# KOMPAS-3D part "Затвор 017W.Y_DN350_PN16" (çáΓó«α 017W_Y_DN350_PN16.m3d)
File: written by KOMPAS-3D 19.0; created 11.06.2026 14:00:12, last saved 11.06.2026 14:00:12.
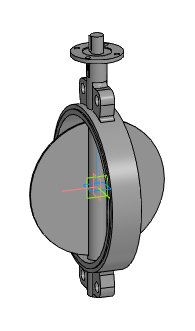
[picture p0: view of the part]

Document properties: Автор: Евгений; Полное имя файла: Z:\3.Личные\kachalov\001_3d для проектировщиков\x.x Тип 017W.Y(S) Затвор дисковый поворотный межфланцевый\_stp_Затвор 017W.Y_DN50-DN350\Затвор 017W_Y_DN350_PN16.m3d

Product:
- Part/product: Затвор 017W.Y_DN350_PN16

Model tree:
1. Операция без истории:1  (labels: Затвор 017W.Y_DN350_PN16)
